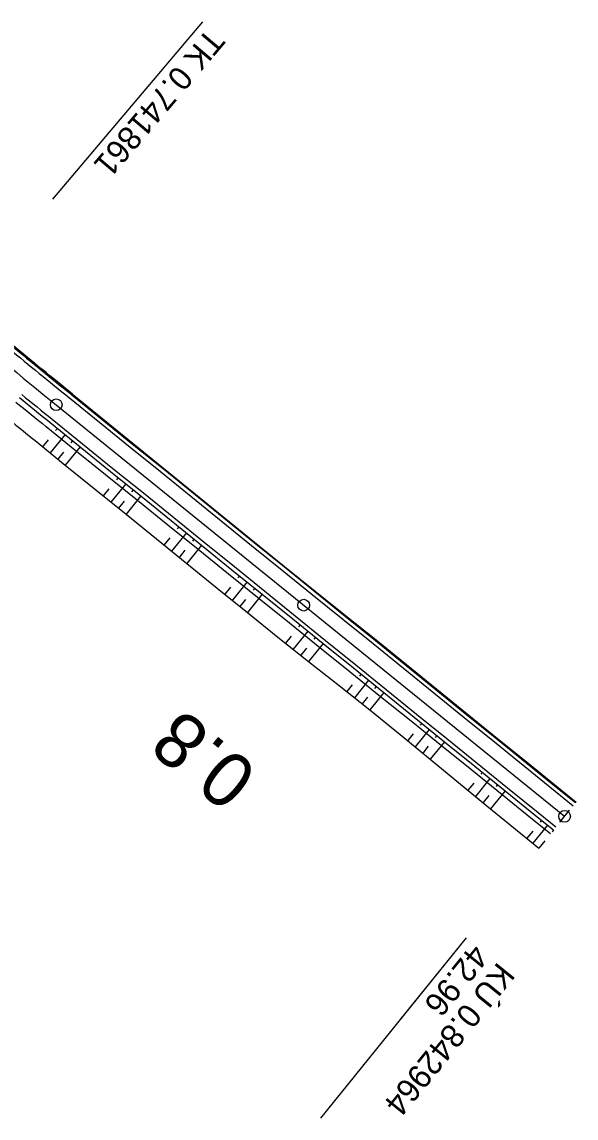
# Model space of a CAD drawing. Extents: x -481656 to -478728, y -1113199 to -1110710.
# Drawn here: x -481173.6 to -481102.7, y -1113199.2 to -1113058.9 of the extents above; entities that cross this region are included whole.
import ezdxf

# ---------------------------------------------------------------- set-up
doc = ezdxf.new("R2010")
doc.units = 0
for name, color, linetype in [('C11_HATCH_SLOPE_L', 7, 'Continuous'), ('C11_HATCH_SLOPE_R', 7, 'Continuous'), ('C11_HECTOMETRY', 7, 'Continuous'), ('C11_HLBODY', 7, 'Continuous'), ('C11_HRANA_TELESO', 7, 'Continuous'), ('C11_KORUNA', 7, 'Continuous'), ('C11_OSA', 7, 'Continuous'), ('C11_PRIKOP', 7, 'Continuous'), ('C11_STANICENI', 7, 'Continuous'), ('C11_VOZOVKA', 7, 'Continuous'), ('C11_ZPEVKRAJ', 7, 'Continuous')]:
    doc.layers.add(name, color=color, linetype=linetype)

msp = doc.modelspace()

# ---------------------------------------------------------------- linework, layer by layer
at = {"layer": 'C11_HATCH_SLOPE_L'}
for p, q in [((-481173.01, -1113101.88), (-481172.92, -1113101.76)), ((-481172.05, -1113102.67), (-481172, -1113102.61)), ((-481171.96, -1113102.56), (-481171.96, -1113102.56)), ((-481171.09, -1113103.46), (-481170.99, -1113103.35)), ((-481166.24, -1113107.4), (-481166.2, -1113107.35)), ((-481166.16, -1113107.3), (-481166.16, -1113107.3)), ((-481165.27, -1113108.18), (-481165.2, -1113108.09)), ((-481164.3, -1113108.97), (-481164.26, -1113108.92)), ((-481164.23, -1113108.88), (-481164.23, -1113108.88)), ((-481163.33, -1113109.76), (-481163.26, -1113109.67)), ((-481158.47, -1113113.69), (-481158.44, -1113113.65)), ((-481158.41, -1113113.61), (-481158.41, -1113113.61)), ((-481157.5, -1113114.47), (-481157.44, -1113114.4)), ((-481156.53, -1113115.26), (-481156.5, -1113115.22)), ((-481156.47, -1113115.19), (-481156.47, -1113115.19)), ((-481155.55, -1113116.04), (-481155.5, -1113115.98)), ((-481150.7, -1113119.98), (-481150.67, -1113119.95)), ((-481150.65, -1113119.92), (-481150.65, -1113119.92)), ((-481149.73, -1113120.76), (-481149.68, -1113120.71)), ((-481148.75, -1113121.55), (-481148.73, -1113121.52)), ((-481148.71, -1113121.5), (-481148.71, -1113121.5)), ((-481147.78, -1113122.34), (-481147.74, -1113122.29)), ((-481142.92, -1113126.27), (-481142.91, -1113126.25)), ((-481142.89, -1113126.23), (-481142.89, -1113126.23)), ((-481141.95, -1113127.05), (-481141.92, -1113127.02)), ((-481140.98, -1113127.84), (-481140.97, -1113127.82)), ((-481140.95, -1113127.8), (-481140.95, -1113127.8)), ((-481140.01, -1113128.63), (-481139.98, -1113128.59)), ((-481135.15, -1113132.56), (-481135.13, -1113132.53)), ((-481135.1, -1113132.5), (-481135.1, -1113132.5)), ((-481134.18, -1113133.35), (-481134.13, -1113133.28)), ((-481133.21, -1113134.13), (-481133.18, -1113134.1)), ((-481133.15, -1113134.07), (-481133.15, -1113134.07)), ((-481132.23, -1113134.92), (-481132.18, -1113134.85)), ((-481127.38, -1113138.85), (-481127.34, -1113138.81)), ((-481127.31, -1113138.77), (-481127.31, -1113138.77)), ((-481126.41, -1113139.64), (-481126.34, -1113139.55)), ((-481125.43, -1113140.42), (-481125.4, -1113140.38)), ((-481125.36, -1113140.33), (-481125.36, -1113140.33)), ((-481124.46, -1113141.21), (-481124.39, -1113141.12)), ((-481119.6, -1113145.14), (-481119.57, -1113145.1)), ((-481119.54, -1113145.06), (-481119.54, -1113145.06)), ((-481118.63, -1113145.93), (-481118.57, -1113145.85)), ((-481117.66, -1113146.71), (-481117.63, -1113146.68)), ((-481117.6, -1113146.64), (-481117.6, -1113146.64)), ((-481116.69, -1113147.5), (-481116.63, -1113147.43)), ((-481111.83, -1113151.43), (-481111.8, -1113151.4)), ((-481111.77, -1113151.36), (-481111.77, -1113151.36)), ((-481110.86, -1113152.22), (-481110.8, -1113152.15)), ((-481109.89, -1113153.01), (-481109.86, -1113152.97)), ((-481109.83, -1113152.94), (-481109.83, -1113152.94)), ((-481108.92, -1113153.79), (-481108.86, -1113153.72)), ((-481104.26, -1113157.56), (-481104.23, -1113157.52)), ((-481104.21, -1113157.49), (-481104.21, -1113157.49)), ((-481103.49, -1113158.18), (-481103.44, -1113158.11)), ((-481102.73, -1113158.8), (-481102.7, -1113158.76)), ((-481102.67, -1113158.73), (-481102.67, -1113158.73))]:
    msp.add_line(p, q, dxfattribs=at)
at = {"layer": 'C11_HATCH_SLOPE_R'}
for p, q in [((-481169.07, -1113110.89), (-481169.3, -1113111.17)), ((-481170.25, -1113112.35), (-481170.97, -1113113.24)), ((-481168.1, -1113111.68), (-481170, -1113114.02)), ((-481167.13, -1113112.47), (-481167.36, -1113112.75)), ((-481168.3, -1113113.92), (-481169.03, -1113114.81)), ((-481166.16, -1113113.25), (-481168.06, -1113115.6)), ((-481161.3, -1113117.18), (-481161.52, -1113117.46)), ((-481162.47, -1113118.63), (-481163.2, -1113119.53)), ((-481160.33, -1113117.97), (-481162.23, -1113120.32)), ((-481158.39, -1113119.54), (-481160.29, -1113121.89)), ((-481159.36, -1113118.76), (-481159.58, -1113119.03)), ((-481160.53, -1113120.2), (-481161.26, -1113121.1)), ((-481152.56, -1113124.26), (-481154.46, -1113126.61)), ((-481153.53, -1113123.48), (-481153.74, -1113123.74)), ((-481154.7, -1113124.92), (-481155.43, -1113125.82)), ((-481151.58, -1113125.05), (-481151.8, -1113125.32)), ((-481152.75, -1113126.49), (-481153.49, -1113127.4)), ((-481150.61, -1113125.83), (-481152.51, -1113128.18)), ((-481145.75, -1113129.77), (-481145.97, -1113130.03)), ((-481146.92, -1113131.21), (-481147.66, -1113132.12)), ((-481144.78, -1113130.55), (-481146.69, -1113132.91)), ((-481142.84, -1113132.12), (-481144.74, -1113134.48)), ((-481143.81, -1113131.34), (-481144.02, -1113131.6)), ((-481144.98, -1113132.78), (-481145.72, -1113133.69)), ((-481137.01, -1113136.84), (-481138.89, -1113139.16)), ((-481137.98, -1113136.06), (-481138.19, -1113136.31)), ((-481139.13, -1113137.48), (-481139.87, -1113138.39)), ((-481136.04, -1113137.63), (-481136.24, -1113137.89)), ((-481137.18, -1113139.04), (-481137.91, -1113139.94)), ((-481135.07, -1113138.42), (-481136.93, -1113140.72)), ((-481130.21, -1113142.35), (-481130.41, -1113142.6)), ((-481131.32, -1113143.72), (-481132.02, -1113144.59)), ((-481129.24, -1113143.13), (-481131.04, -1113145.37)), ((-481128.26, -1113143.92), (-481128.47, -1113144.17)), ((-481129.37, -1113145.28), (-481130.06, -1113146.14)), ((-481127.29, -1113144.71), (-481129.08, -1113146.92)), ((-481121.46, -1113149.43), (-481123.27, -1113151.66)), ((-481122.43, -1113148.64), (-481122.63, -1113148.88)), ((-481123.53, -1113150), (-481124.23, -1113150.86)), ((-481120.49, -1113150.21), (-481120.69, -1113150.46)), ((-481121.59, -1113151.58), (-481122.3, -1113152.45)), ((-481119.52, -1113151), (-481121.34, -1113153.25)), ((-481114.66, -1113154.93), (-481114.85, -1113155.17)), ((-481115.78, -1113156.31), (-481116.51, -1113157.22)), ((-481113.69, -1113155.72), (-481115.54, -1113158.01)), ((-481112.72, -1113156.5), (-481112.91, -1113156.74)), ((-481113.84, -1113157.89), (-481114.58, -1113158.8)), ((-481111.75, -1113157.29), (-481113.61, -1113159.6)), ((-481106.33, -1113161.68), (-481108.2, -1113163.99)), ((-481107.09, -1113161.05), (-481107.28, -1113161.29)), ((-481108.22, -1113162.45), (-481108.97, -1113163.37)), ((-481105.56, -1113162.3), (-481105.75, -1113162.53)), ((-481106.68, -1113163.69), (-481107.43, -1113164.61))]:
    msp.add_line(p, q, dxfattribs=at)
at = {"layer": 'C11_HECTOMETRY'}
msp.add_circle((-481137.54, -1113133.52), 0.75, dxfattribs=at)
at = {"layer": 'C11_HLBODY'}
for p, q in [((-481150.51, -1113058.86), (-481169.69, -1113081.53)), ((-481116.72, -1113176.1), (-481135.41, -1113199.18))]:
    msp.add_line(p, q, dxfattribs=at)
for centre in [(-481169.23, -1113107.87), (-481104.14, -1113160.55)]:
    msp.add_circle(centre, 0.75, dxfattribs=at)
at = {"layer": 'C11_HRANA_TELESO'}
for p, q in [((-481167.13, -1113106.51), (-481163.26, -1113109.67)), ((-481163.26, -1113109.67), (-481159.38, -1113112.82)), ((-481171.94, -1113112.45), (-481168.06, -1113115.6)), ((-481159.38, -1113112.82), (-481155.5, -1113115.98)), ((-481168.06, -1113115.6), (-481164.17, -1113118.74)), ((-481155.5, -1113115.98), (-481151.62, -1113119.13)), ((-481164.17, -1113118.74), (-481160.29, -1113121.89)), ((-481151.62, -1113119.13), (-481147.74, -1113122.29)), ((-481160.29, -1113121.89), (-481156.4, -1113125.04)), ((-481147.74, -1113122.29), (-481143.86, -1113125.44)), ((-481156.4, -1113125.04), (-481152.51, -1113128.18)), ((-481143.86, -1113125.44), (-481139.98, -1113128.59)), ((-481152.51, -1113128.18), (-481148.63, -1113131.33)), ((-481139.98, -1113128.59), (-481136.08, -1113131.72)), ((-481148.63, -1113131.33), (-481144.74, -1113134.48)), ((-481136.08, -1113131.72), (-481132.18, -1113134.85)), ((-481144.74, -1113134.48), (-481140.85, -1113137.61)), ((-481132.18, -1113134.85), (-481128.28, -1113137.98)), ((-481140.85, -1113137.61), (-481136.93, -1113140.72)), ((-481128.28, -1113137.98), (-481124.39, -1113141.12)), ((-481136.93, -1113140.72), (-481133, -1113143.82)), ((-481124.39, -1113141.12), (-481120.51, -1113144.27)), ((-481133, -1113143.82), (-481129.08, -1113146.92)), ((-481120.51, -1113144.27), (-481116.63, -1113147.43)), ((-481129.08, -1113146.92), (-481125.2, -1113150.07)), ((-481116.63, -1113147.43), (-481112.74, -1113150.57)), ((-481125.2, -1113150.07), (-481121.34, -1113153.25)), ((-481112.74, -1113150.57), (-481108.86, -1113153.72)), ((-481121.34, -1113153.25), (-481117.48, -1113156.42)), ((-481108.86, -1113153.72), (-481104.97, -1113156.87)), ((-481117.48, -1113156.42), (-481113.61, -1113159.6)), ((-481104.97, -1113156.87), (-481102.67, -1113158.73)), ((-481113.61, -1113159.6), (-481109.73, -1113162.75)), ((-481109.73, -1113162.75), (-481107.43, -1113164.61))]:
    msp.add_line(p, q, dxfattribs=at)
for centre, radius, start, end in [((-480663.63, -1112487.93), 797.6, 230.13918, 230.49729), ((-481421.48, -1113413.68), 398.8, 50.3738, 51.0904), ((-480919.6, -1112798.7), 402.63, 230.4755, 231.191)]:
    msp.add_arc(centre, radius, start, end, dxfattribs=at)
at = {"layer": 'C11_KORUNA'}
for p, q in [((-481167.22, -1113106.61), (-481163.33, -1113109.76)), ((-481170.05, -1113110.11), (-481166.16, -1113113.25)), ((-481163.33, -1113109.76), (-481159.44, -1113112.9)), ((-481159.44, -1113112.9), (-481155.55, -1113116.04)), ((-481166.16, -1113113.25), (-481162.27, -1113116.4)), ((-481162.27, -1113116.4), (-481158.39, -1113119.54)), ((-481155.55, -1113116.04), (-481151.67, -1113119.19)), ((-481158.39, -1113119.54), (-481154.5, -1113122.69)), ((-481151.67, -1113119.19), (-481147.78, -1113122.34)), ((-481154.5, -1113122.69), (-481150.61, -1113125.83)), ((-481147.78, -1113122.34), (-481143.9, -1113125.48)), ((-481143.9, -1113125.48), (-481140.01, -1113128.63)), ((-481150.61, -1113125.83), (-481146.73, -1113128.98)), ((-481146.73, -1113128.98), (-481142.84, -1113132.12)), ((-481140.01, -1113128.63), (-481136.12, -1113131.77)), ((-481142.84, -1113132.12), (-481138.95, -1113135.27)), ((-481136.12, -1113131.77), (-481132.23, -1113134.92)), ((-481138.95, -1113135.27), (-481135.07, -1113138.42)), ((-481132.23, -1113134.92), (-481128.35, -1113138.06)), ((-481128.35, -1113138.06), (-481124.46, -1113141.21)), ((-481135.07, -1113138.42), (-481131.18, -1113141.56)), ((-481131.18, -1113141.56), (-481127.29, -1113144.71)), ((-481124.46, -1113141.21), (-481120.58, -1113144.35)), ((-481127.29, -1113144.71), (-481123.41, -1113147.85)), ((-481120.58, -1113144.35), (-481116.69, -1113147.5)), ((-481123.41, -1113147.85), (-481119.52, -1113151)), ((-481116.69, -1113147.5), (-481112.8, -1113150.65)), ((-481112.8, -1113150.65), (-481108.92, -1113153.79)), ((-481119.52, -1113151), (-481115.63, -1113154.14)), ((-481115.63, -1113154.14), (-481111.75, -1113157.29)), ((-481108.92, -1113153.79), (-481105.03, -1113156.94)), ((-481111.75, -1113157.29), (-481107.86, -1113160.43)), ((-481105.03, -1113156.94), (-481102.73, -1113158.8)), ((-481107.86, -1113160.43), (-481105.56, -1113162.3))]:
    msp.add_line(p, q, dxfattribs=at)
for centre, radius, start, end in [((-480665.96, -1112486.01), 797.75, 230.35582, 230.71392), ((-480917.53, -1112795.55), 398.88, 230.5305, 231.247), ((-480918.95, -1112797.29), 401.12, 230.5307, 231.2466)]:
    msp.add_arc(centre, radius, start, end, dxfattribs=at)
at = {"layer": 'C11_OSA'}
msp.add_line((-481169.23, -1113107.87), (-481104.14, -1113160.55), dxfattribs=at)
msp.add_arc((-480665.96, -1112486.01), 800, 229.77294, 231.01682, dxfattribs=at)
at = {"layer": 'C11_PRIKOP'}
for p, q in [((-481170.5, -1113110.67), (-481166.61, -1113113.81)), ((-481166.61, -1113113.81), (-481162.72, -1113116.95)), ((-481162.72, -1113116.95), (-481158.83, -1113120.09)), ((-481158.83, -1113120.09), (-481154.94, -1113123.23)), ((-481154.94, -1113123.23), (-481151.04, -1113126.37)), ((-481151.04, -1113126.37), (-481147.15, -1113129.51)), ((-481147.15, -1113129.51), (-481143.26, -1113132.65)), ((-481143.26, -1113132.65), (-481139.37, -1113135.79)), ((-481139.37, -1113135.79), (-481135.48, -1113138.93)), ((-481135.48, -1113138.93), (-481131.59, -1113142.07)), ((-481131.59, -1113142.07), (-481127.7, -1113145.21)), ((-481127.7, -1113145.21), (-481123.8, -1113148.34)), ((-481123.8, -1113148.34), (-481119.91, -1113151.49)), ((-481119.91, -1113151.49), (-481116.02, -1113154.62)), ((-481116.02, -1113154.62), (-481112.13, -1113157.76)), ((-481112.13, -1113157.76), (-481108.24, -1113160.9)), ((-481108.24, -1113160.9), (-481105.93, -1113162.76))]:
    msp.add_line(p, q, dxfattribs=at)
msp.add_arc((-480919.65, -1112797.19), 401.49, 230.6175, 231.3333, dxfattribs=at)
at = {"layer": 'C11_STANICENI'}
for p, q in [((-481104.77, -1113161.32), (-481103.51, -1113159.77)), ((-481116.73, -1113176.09), (-481125.22, -1113186.59))]:
    msp.add_line(p, q, dxfattribs=at)
at = {"layer": 'C11_VOZOVKA'}
for p, q in [((-481167.53, -1113107), (-481163.64, -1113110.14)), ((-481169.73, -1113109.72), (-481165.85, -1113112.86)), ((-481163.64, -1113110.14), (-481159.76, -1113113.29)), ((-481165.85, -1113112.86), (-481161.96, -1113116.01)), ((-481159.76, -1113113.29), (-481155.87, -1113116.43)), ((-481161.96, -1113116.01), (-481158.07, -1113119.16)), ((-481155.87, -1113116.43), (-481151.98, -1113119.58)), ((-481158.07, -1113119.16), (-481154.18, -1113122.3)), ((-481151.98, -1113119.58), (-481148.1, -1113122.73)), ((-481154.18, -1113122.3), (-481150.3, -1113125.45)), ((-481148.1, -1113122.73), (-481144.21, -1113125.87)), ((-481150.3, -1113125.45), (-481146.41, -1113128.59)), ((-481144.21, -1113125.87), (-481140.32, -1113129.02)), ((-481146.41, -1113128.59), (-481142.53, -1113131.74)), ((-481140.32, -1113129.02), (-481136.44, -1113132.16)), ((-481142.53, -1113131.74), (-481138.64, -1113134.88)), ((-481136.44, -1113132.16), (-481132.55, -1113135.31)), ((-481138.64, -1113134.88), (-481134.75, -1113138.03)), ((-481132.55, -1113135.31), (-481128.66, -1113138.45)), ((-481134.75, -1113138.03), (-481130.86, -1113141.17)), ((-481128.66, -1113138.45), (-481124.78, -1113141.6)), ((-481130.86, -1113141.17), (-481126.98, -1113144.32)), ((-481124.78, -1113141.6), (-481120.89, -1113144.74)), ((-481126.98, -1113144.32), (-481123.09, -1113147.46)), ((-481120.89, -1113144.74), (-481117, -1113147.89)), ((-481123.09, -1113147.46), (-481119.21, -1113150.61)), ((-481117, -1113147.89), (-481113.12, -1113151.03)), ((-481119.21, -1113150.61), (-481115.32, -1113153.76)), ((-481113.12, -1113151.03), (-481109.23, -1113154.18)), ((-481115.32, -1113153.76), (-481111.43, -1113156.9)), ((-481109.23, -1113154.18), (-481105.34, -1113157.32)), ((-481111.43, -1113156.9), (-481107.54, -1113160.05)), ((-481105.34, -1113157.32), (-481103.04, -1113159.19)), ((-481107.54, -1113160.05), (-481105.24, -1113161.91))]:
    msp.add_line(p, q, dxfattribs=at)
for centre, radius, start, end in [((-480665.96, -1112486.01), 798.25, 230.35582, 230.71392), ((-480917.69, -1112795.74), 399.12, 230.5305, 231.247), ((-480918.8, -1112797.1), 400.88, 230.5307, 231.2466)]:
    msp.add_arc(centre, radius, start, end, dxfattribs=at)
at = {"layer": 'C11_ZPEVKRAJ'}
for p, q in [((-481167.53, -1113107), (-481163.64, -1113110.14)), ((-481169.73, -1113109.72), (-481165.85, -1113112.86)), ((-481163.64, -1113110.14), (-481159.76, -1113113.29)), ((-481165.85, -1113112.86), (-481161.96, -1113116.01)), ((-481159.76, -1113113.29), (-481155.87, -1113116.43)), ((-481161.96, -1113116.01), (-481158.07, -1113119.16)), ((-481155.87, -1113116.43), (-481151.98, -1113119.58)), ((-481158.07, -1113119.16), (-481154.18, -1113122.3)), ((-481151.98, -1113119.58), (-481148.1, -1113122.73)), ((-481154.18, -1113122.3), (-481150.3, -1113125.45)), ((-481148.1, -1113122.73), (-481144.21, -1113125.87)), ((-481150.3, -1113125.45), (-481146.41, -1113128.59)), ((-481144.21, -1113125.87), (-481140.32, -1113129.02)), ((-481146.41, -1113128.59), (-481142.53, -1113131.74)), ((-481140.32, -1113129.02), (-481136.44, -1113132.16)), ((-481142.53, -1113131.74), (-481138.64, -1113134.88)), ((-481136.44, -1113132.16), (-481132.55, -1113135.31)), ((-481138.64, -1113134.88), (-481134.75, -1113138.03)), ((-481132.55, -1113135.31), (-481128.66, -1113138.45)), ((-481134.75, -1113138.03), (-481130.86, -1113141.17)), ((-481128.66, -1113138.45), (-481124.78, -1113141.6)), ((-481130.86, -1113141.17), (-481126.98, -1113144.32)), ((-481124.78, -1113141.6), (-481120.89, -1113144.74)), ((-481126.98, -1113144.32), (-481123.09, -1113147.46)), ((-481120.89, -1113144.74), (-481117, -1113147.89)), ((-481123.09, -1113147.46), (-481119.21, -1113150.61)), ((-481117, -1113147.89), (-481113.12, -1113151.03)), ((-481119.21, -1113150.61), (-481115.32, -1113153.76)), ((-481113.12, -1113151.03), (-481109.23, -1113154.18)), ((-481115.32, -1113153.76), (-481111.43, -1113156.9)), ((-481109.23, -1113154.18), (-481105.34, -1113157.32)), ((-481111.43, -1113156.9), (-481107.54, -1113160.05)), ((-481105.34, -1113157.32), (-481103.04, -1113159.19)), ((-481107.54, -1113160.05), (-481105.24, -1113161.91))]:
    msp.add_line(p, q, dxfattribs=at)
for centre, radius, start, end in [((-480665.96, -1112486.01), 798.25, 230.35582, 230.71392), ((-480917.69, -1112795.74), 399.12, 230.5305, 231.247), ((-480918.8, -1112797.1), 400.88, 230.5307, 231.2466)]:
    msp.add_arc(centre, radius, start, end, dxfattribs=at)

# ---------------------------------------------------------------- texts
at = {"layer": 'C11_HECTOMETRY'}
msp.add_text('0.8', height=7, rotation=140.9712, dxfattribs=at).set_placement((-481143.1, -1113154.76))
at = {"layer": 'C11_HLBODY'}
for s, rotation, p in [('TK 0.741861', 229.7729, (-481149.75, -1113059.5)), ('KÚ 0.842964', 231.0168, (-481112.65, -1113179.08))]:
    msp.add_text(s, height=2.999, rotation=rotation, dxfattribs=at).set_placement(p)
at = {"layer": 'C11_STANICENI'}
msp.add_text('42.96', height=2.999, rotation=231.0168, dxfattribs=at).set_placement((-481115.95, -1113176.72))

doc.saveas('drawing.dxf')
